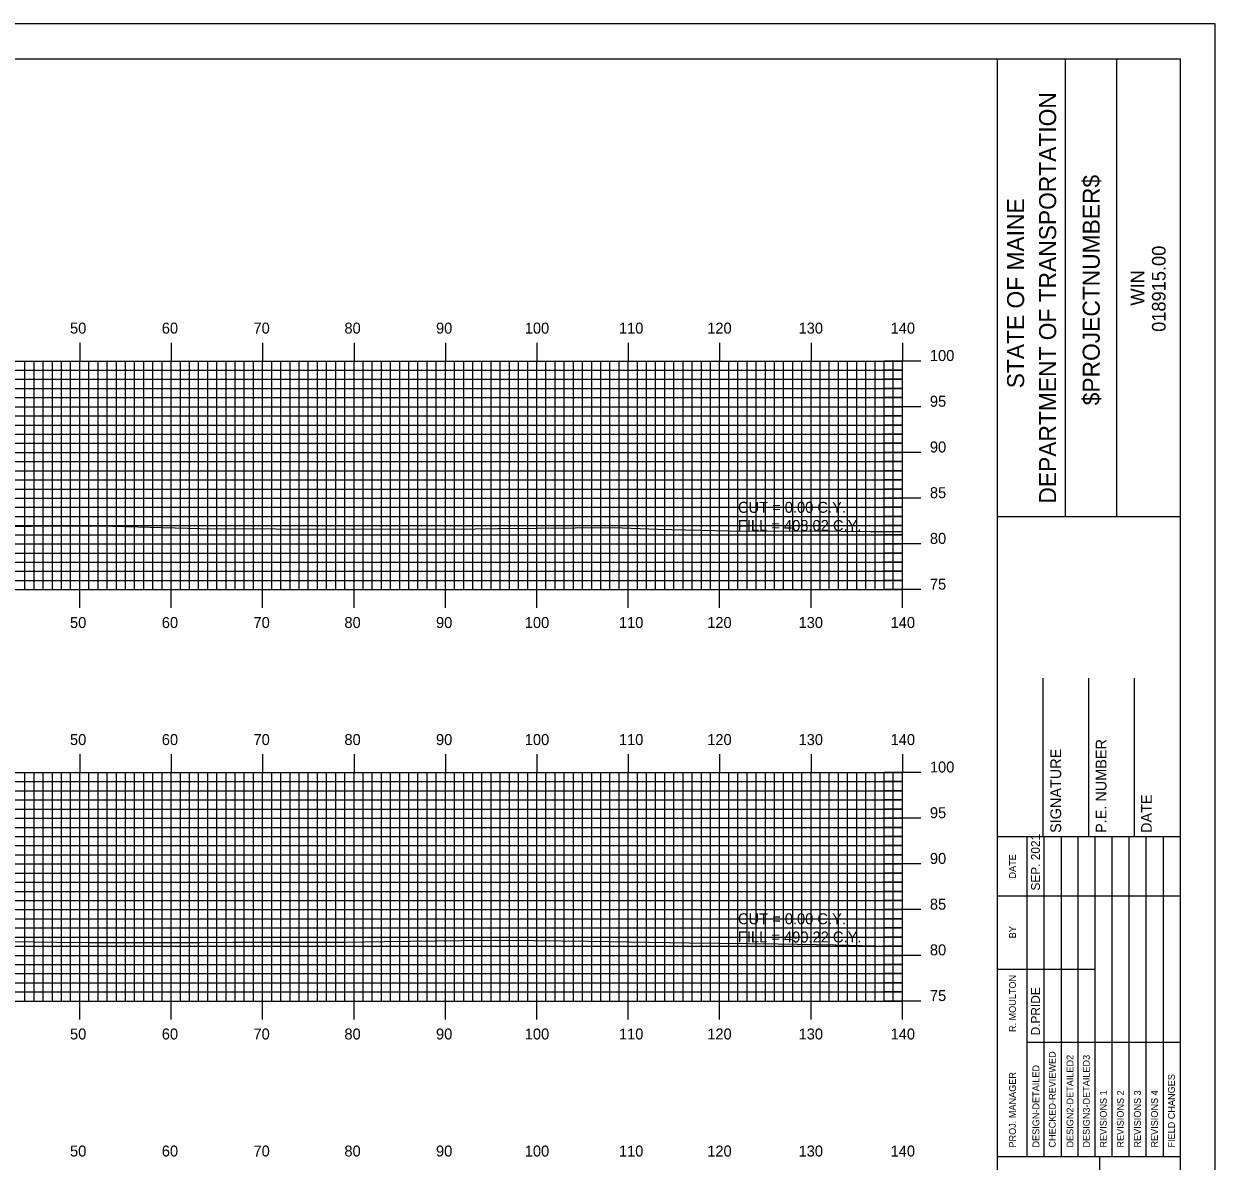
# Model space of a CAD drawing. Extents: x 853723 to 854066, y 364366 to 364586.
# Drawn here: x 853932.6 to 854062.9, y 364461.3 to 364585.7 of the extents above; entities that cross this region are included whole.
import ezdxf

# ---------------------------------------------------------------- set-up
doc = ezdxf.new("R2010")
doc.units = 0
for name, color, linetype in [('BORDER', 7, 'Continuous'), ('D_Text_Standard', 7, 'Continuous'), ('H_V ANNOTATION', 7, 'Continuous'), ('MAJOR', 7, 'Continuous'), ('MINOR', 7, 'Continuous'), ('PLOT BOUNDARY', 7, 'Continuous'), ('S_Roadway_Centerline', 7, 'Continuous')]:
    doc.layers.add(name, color=color, linetype=linetype)

msp = doc.modelspace()

# ---------------------------------------------------------------- linework, layer by layer
at = {"layer": 'BORDER'}
for p, q in [((854039.12, 364371.79), (854039.12, 364581.79)), ((854046.57, 364531.78), (854046.57, 364581.78)), ((854052.16, 364531.78), (854052.16, 364581.78)), ((854039.12, 364531.78), (854059.12, 364531.78)), ((854044.12, 364496.79), (854044.12, 364514.09)), ((854049.12, 364496.79), (854049.12, 364514.09)), ((854054.12, 364496.79), (854054.12, 364514.09)), ((854039.12, 364496.79), (854059.12, 364496.79)), ((854039.12, 364461.79), (854059.12, 364461.79)), ((854050.3, 364391.79), (854050.3, 364461.79))]:
    msp.add_line(p, q, dxfattribs=at)
msp.add_lwpolyline([(853739.12, 364371.79), (854059.12, 364371.79), (854059.12, 364581.79), (853739.12, 364581.79)], close=True, dxfattribs=at)
for points in [[(854042.35, 364490.29), (854042.35, 364496.79)], [(854044.21, 364461.8), (854044.21, 364496.79)], [(854046.08, 364496.79), (854046.08, 364461.8)], [(854047.94, 364461.8), (854047.94, 364496.79)], [(854049.8, 364461.8), (854049.8, 364496.79)], [(854051.67, 364461.8), (854051.67, 364496.79)], [(854053.53, 364461.8), (854053.53, 364496.79)], [(854055.39, 364461.8), (854055.39, 364496.79)], [(854057.26, 364461.8), (854057.26, 364496.79)], [(854042.35, 364461.8), (854042.35, 364495.38)], [(854039.12, 364490.29), (854059.12, 364490.29)], [(854039.12, 364482.29), (854042.35, 364482.29)], [(854042.35, 364482.29), (854049.8, 364482.29)], [(854042.35, 364474.29), (854059.12, 364474.29)]]:
    msp.add_lwpolyline(points, dxfattribs=at)
at = {"layer": 'MAJOR'}
for p, q in [((853938.72, 364550.79), (853938.72, 364548.79)), ((853948.72, 364550.79), (853948.72, 364548.79)), ((853958.72, 364550.79), (853958.72, 364548.79)), ((853968.72, 364550.79), (853968.72, 364548.79)), ((853978.72, 364550.79), (853978.72, 364548.79)), ((853988.72, 364550.79), (853988.72, 364548.79)), ((853998.72, 364550.79), (853998.72, 364548.79)), ((854008.72, 364550.79), (854008.72, 364548.79)), ((854018.72, 364550.79), (854018.72, 364548.79)), ((854028.72, 364550.79), (854028.72, 364548.79)), ((853748.72, 364548.79), (854028.72, 364548.79)), ((853748.72, 364548.79), (854028.72, 364548.79)), ((853938.72, 364523.79), (853938.72, 364548.79)), ((853948.72, 364523.79), (853948.72, 364548.79)), ((853958.72, 364523.79), (853958.72, 364548.79)), ((853968.72, 364523.79), (853968.72, 364548.79)), ((853978.72, 364523.79), (853978.72, 364548.79)), ((853988.72, 364523.79), (853988.72, 364548.79)), ((853998.72, 364523.79), (853998.72, 364548.79)), ((854008.72, 364523.79), (854008.72, 364548.79)), ((854018.72, 364523.79), (854018.72, 364548.79)), ((854030.72, 364548.79), (854026.71, 364548.79)), ((854028.72, 364523.79), (854028.72, 364548.79)), ((854028.72, 364523.79), (854028.72, 364548.79)), ((853748.72, 364543.79), (854028.72, 364543.79)), ((854030.72, 364543.79), (854026.71, 364543.79)), ((853748.72, 364538.79), (854028.72, 364538.79)), ((854030.72, 364538.79), (854026.71, 364538.79)), ((853748.72, 364533.79), (854028.72, 364533.79)), ((854030.72, 364533.79), (854026.71, 364533.79)), ((853748.72, 364528.79), (854028.72, 364528.79)), ((854030.72, 364528.79), (854026.71, 364528.79)), ((853748.72, 364523.79), (854028.72, 364523.79)), ((853748.72, 364523.79), (854028.72, 364523.79)), ((853938.72, 364521.78), (853938.72, 364523.79)), ((853948.72, 364521.78), (853948.72, 364523.79)), ((853958.72, 364521.78), (853958.72, 364523.79)), ((853968.72, 364521.78), (853968.72, 364523.79)), ((853978.72, 364521.78), (853978.72, 364523.79)), ((853988.72, 364521.78), (853988.72, 364523.79)), ((853998.72, 364521.78), (853998.72, 364523.79)), ((854008.72, 364521.78), (854008.72, 364523.79)), ((854018.72, 364521.78), (854018.72, 364523.79)), ((854030.72, 364523.79), (854026.71, 364523.79)), ((854028.72, 364521.78), (854028.72, 364523.79)), ((853938.72, 364505.79), (853938.72, 364503.79)), ((853948.72, 364505.79), (853948.72, 364503.79)), ((853958.72, 364505.79), (853958.72, 364503.79)), ((853968.72, 364505.79), (853968.72, 364503.79)), ((853978.72, 364505.79), (853978.72, 364503.79)), ((853988.72, 364505.79), (853988.72, 364503.79)), ((853998.72, 364505.79), (853998.72, 364503.79)), ((854008.72, 364505.79), (854008.72, 364503.79)), ((854018.72, 364505.79), (854018.72, 364503.79)), ((854028.72, 364505.79), (854028.72, 364503.79)), ((853748.72, 364503.79), (854028.72, 364503.79)), ((853748.72, 364503.79), (854028.72, 364503.79)), ((853938.72, 364478.79), (853938.72, 364503.79)), ((853948.72, 364478.79), (853948.72, 364503.79)), ((853958.72, 364478.79), (853958.72, 364503.79)), ((853968.72, 364478.79), (853968.72, 364503.79)), ((853978.72, 364478.79), (853978.72, 364503.79)), ((853988.72, 364478.79), (853988.72, 364503.79)), ((853998.72, 364478.79), (853998.72, 364503.79)), ((854008.72, 364478.79), (854008.72, 364503.79)), ((854018.72, 364478.79), (854018.72, 364503.79)), ((854030.72, 364503.79), (854026.71, 364503.79)), ((854028.72, 364478.79), (854028.72, 364503.79)), ((854028.72, 364478.79), (854028.72, 364503.79)), ((853748.72, 364498.79), (854028.72, 364498.79)), ((854030.72, 364498.79), (854026.71, 364498.79)), ((853748.72, 364493.79), (854028.72, 364493.79)), ((854030.72, 364493.79), (854026.71, 364493.79)), ((853748.72, 364488.79), (854028.72, 364488.79)), ((854030.72, 364488.79), (854026.71, 364488.79)), ((853748.72, 364483.79), (854028.72, 364483.79)), ((854030.72, 364483.79), (854026.71, 364483.79)), ((853748.72, 364478.79), (854028.72, 364478.79)), ((853748.72, 364478.79), (854028.72, 364478.79)), ((853938.72, 364476.78), (853938.72, 364478.79)), ((853948.72, 364476.78), (853948.72, 364478.79)), ((853958.72, 364476.78), (853958.72, 364478.79)), ((853968.72, 364476.78), (853968.72, 364478.79)), ((853978.72, 364476.78), (853978.72, 364478.79)), ((853988.72, 364476.78), (853988.72, 364478.79)), ((853998.72, 364476.78), (853998.72, 364478.79)), ((854008.72, 364476.78), (854008.72, 364478.79)), ((854018.72, 364476.78), (854018.72, 364478.79)), ((854030.72, 364478.79), (854026.71, 364478.79)), ((854028.72, 364476.78), (854028.72, 364478.79))]:
    msp.add_line(p, q, dxfattribs=at)
at = {"layer": 'MINOR'}
for p, q in [((853748.72, 364547.79), (854028.72, 364547.79)), ((853932.72, 364523.79), (853932.72, 364548.79)), ((853933.72, 364523.79), (853933.72, 364548.79)), ((853934.72, 364523.79), (853934.72, 364548.79)), ((853935.72, 364523.79), (853935.72, 364548.79)), ((853936.72, 364523.79), (853936.72, 364548.79)), ((853937.72, 364523.79), (853937.72, 364548.79)), ((853939.72, 364523.79), (853939.72, 364548.79)), ((853940.72, 364523.79), (853940.72, 364548.79)), ((853941.72, 364523.79), (853941.72, 364548.79)), ((853942.72, 364523.79), (853942.72, 364548.79)), ((853943.72, 364523.79), (853943.72, 364548.79)), ((853944.72, 364523.79), (853944.72, 364548.79)), ((853945.72, 364523.79), (853945.72, 364548.79)), ((853946.72, 364523.79), (853946.72, 364548.79)), ((853947.72, 364523.79), (853947.72, 364548.79)), ((853949.72, 364523.79), (853949.72, 364548.79)), ((853950.72, 364523.79), (853950.72, 364548.79)), ((853951.72, 364523.79), (853951.72, 364548.79)), ((853952.72, 364523.79), (853952.72, 364548.79)), ((853953.72, 364523.79), (853953.72, 364548.79)), ((853954.72, 364523.79), (853954.72, 364548.79)), ((853955.72, 364523.79), (853955.72, 364548.79)), ((853956.72, 364523.79), (853956.72, 364548.79)), ((853957.72, 364523.79), (853957.72, 364548.79)), ((853959.72, 364523.79), (853959.72, 364548.79)), ((853960.72, 364523.79), (853960.72, 364548.79)), ((853961.72, 364523.79), (853961.72, 364548.79)), ((853962.72, 364523.79), (853962.72, 364548.79)), ((853963.72, 364523.79), (853963.72, 364548.79)), ((853964.72, 364523.79), (853964.72, 364548.79)), ((853965.72, 364523.79), (853965.72, 364548.79)), ((853966.72, 364523.79), (853966.72, 364548.79)), ((853967.72, 364523.79), (853967.72, 364548.79)), ((853969.72, 364523.79), (853969.72, 364548.79)), ((853970.72, 364523.79), (853970.72, 364548.79)), ((853971.72, 364523.79), (853971.72, 364548.79)), ((853972.72, 364523.79), (853972.72, 364548.79)), ((853973.72, 364523.79), (853973.72, 364548.79)), ((853974.72, 364523.79), (853974.72, 364548.79)), ((853975.72, 364523.79), (853975.72, 364548.79)), ((853976.72, 364523.79), (853976.72, 364548.79)), ((853977.72, 364523.79), (853977.72, 364548.79)), ((853979.72, 364523.79), (853979.72, 364548.79)), ((853980.72, 364523.79), (853980.72, 364548.79)), ((853981.72, 364523.79), (853981.72, 364548.79)), ((853982.72, 364523.79), (853982.72, 364548.79)), ((853983.72, 364523.79), (853983.72, 364548.79)), ((853984.72, 364523.79), (853984.72, 364548.79)), ((853985.72, 364523.79), (853985.72, 364548.79)), ((853986.72, 364523.79), (853986.72, 364548.79)), ((853987.72, 364523.79), (853987.72, 364548.79)), ((853989.72, 364523.79), (853989.72, 364548.79)), ((853990.72, 364523.79), (853990.72, 364548.79)), ((853991.72, 364523.79), (853991.72, 364548.79)), ((853992.72, 364523.79), (853992.72, 364548.79)), ((853993.72, 364523.79), (853993.72, 364548.79)), ((853994.72, 364523.79), (853994.72, 364548.79)), ((853995.72, 364523.79), (853995.72, 364548.79)), ((853996.72, 364523.79), (853996.72, 364548.79)), ((853997.72, 364523.79), (853997.72, 364548.79)), ((853999.72, 364523.79), (853999.72, 364548.79)), ((854000.72, 364523.79), (854000.72, 364548.79)), ((854001.72, 364523.79), (854001.72, 364548.79)), ((854002.72, 364523.79), (854002.72, 364548.79)), ((854003.72, 364523.79), (854003.72, 364548.79)), ((854004.72, 364523.79), (854004.72, 364548.79)), ((854005.72, 364523.79), (854005.72, 364548.79)), ((854006.72, 364523.79), (854006.72, 364548.79)), ((854007.72, 364523.79), (854007.72, 364548.79)), ((854009.72, 364523.79), (854009.72, 364548.79)), ((854010.72, 364523.79), (854010.72, 364548.79)), ((854011.72, 364523.79), (854011.72, 364548.79)), ((854012.72, 364523.79), (854012.72, 364548.79)), ((854013.72, 364523.79), (854013.72, 364548.79)), ((854014.72, 364523.79), (854014.72, 364548.79)), ((854015.72, 364523.79), (854015.72, 364548.79)), ((854016.72, 364523.79), (854016.72, 364548.79)), ((854017.72, 364523.79), (854017.72, 364548.79)), ((854019.72, 364523.79), (854019.72, 364548.79)), ((854020.72, 364523.79), (854020.72, 364548.79)), ((854021.72, 364523.79), (854021.72, 364548.79)), ((854022.72, 364523.79), (854022.72, 364548.79)), ((854023.72, 364523.79), (854023.72, 364548.79)), ((854024.72, 364523.79), (854024.72, 364548.79)), ((854025.72, 364523.79), (854025.72, 364548.79)), ((854028.72, 364547.79), (854026.71, 364547.79)), ((854026.72, 364523.79), (854026.72, 364548.79)), ((854027.72, 364523.79), (854027.72, 364548.79)), ((853748.72, 364546.79), (854028.72, 364546.79)), ((854028.72, 364546.79), (854026.71, 364546.79)), ((853748.72, 364545.79), (854028.72, 364545.79)), ((854028.72, 364545.79), (854026.71, 364545.79)), ((853748.72, 364544.79), (854028.72, 364544.79)), ((854028.72, 364544.79), (854026.71, 364544.79)), ((853748.72, 364542.79), (854028.72, 364542.79)), ((854028.72, 364542.79), (854026.71, 364542.79)), ((853748.72, 364541.79), (854028.72, 364541.79)), ((854028.72, 364541.79), (854026.71, 364541.79)), ((853748.72, 364540.79), (854028.72, 364540.79)), ((854028.72, 364540.79), (854026.71, 364540.79)), ((853748.72, 364539.79), (854028.72, 364539.79)), ((854028.72, 364539.79), (854026.71, 364539.79)), ((853748.72, 364537.79), (854028.72, 364537.79)), ((854028.72, 364537.79), (854026.71, 364537.79)), ((853748.72, 364536.79), (854028.72, 364536.79)), ((854028.72, 364536.79), (854026.71, 364536.79)), ((853748.72, 364535.79), (854028.72, 364535.79)), ((853748.72, 364534.79), (854028.72, 364534.79)), ((854028.72, 364535.79), (854026.71, 364535.79)), ((854028.72, 364534.79), (854026.71, 364534.79)), ((853748.72, 364532.79), (854028.72, 364532.79)), ((854028.72, 364532.79), (854026.71, 364532.79)), ((853748.72, 364531.79), (854028.72, 364531.79)), ((853748.72, 364530.79), (854028.72, 364530.79)), ((854028.72, 364531.79), (854026.71, 364531.79)), ((854028.72, 364530.79), (854026.71, 364530.79)), ((853748.72, 364529.79), (854028.72, 364529.79)), ((854028.72, 364529.79), (854026.71, 364529.79)), ((853748.72, 364527.79), (854028.72, 364527.79)), ((853748.72, 364526.79), (854028.72, 364526.79)), ((854028.72, 364527.79), (854026.71, 364527.79)), ((854028.72, 364526.79), (854026.71, 364526.79)), ((853748.72, 364525.79), (854028.72, 364525.79)), ((854028.72, 364525.79), (854026.71, 364525.79)), ((853748.72, 364524.79), (854028.72, 364524.79)), ((854028.72, 364524.79), (854026.71, 364524.79)), ((853932.72, 364478.79), (853932.72, 364503.79)), ((853933.72, 364478.79), (853933.72, 364503.79)), ((853934.72, 364478.79), (853934.72, 364503.79)), ((853935.72, 364478.79), (853935.72, 364503.79)), ((853936.72, 364478.79), (853936.72, 364503.79)), ((853937.72, 364478.79), (853937.72, 364503.79)), ((853939.72, 364478.79), (853939.72, 364503.79)), ((853940.72, 364478.79), (853940.72, 364503.79)), ((853941.72, 364478.79), (853941.72, 364503.79)), ((853942.72, 364478.79), (853942.72, 364503.79)), ((853943.72, 364478.79), (853943.72, 364503.79)), ((853944.72, 364478.79), (853944.72, 364503.79)), ((853945.72, 364478.79), (853945.72, 364503.79)), ((853946.72, 364478.79), (853946.72, 364503.79)), ((853947.72, 364478.79), (853947.72, 364503.79)), ((853949.72, 364478.79), (853949.72, 364503.79)), ((853950.72, 364478.79), (853950.72, 364503.79)), ((853951.72, 364478.79), (853951.72, 364503.79)), ((853952.72, 364478.79), (853952.72, 364503.79)), ((853953.72, 364478.79), (853953.72, 364503.79)), ((853954.72, 364478.79), (853954.72, 364503.79)), ((853955.72, 364478.79), (853955.72, 364503.79)), ((853956.72, 364478.79), (853956.72, 364503.79)), ((853957.72, 364478.79), (853957.72, 364503.79)), ((853959.72, 364478.79), (853959.72, 364503.79)), ((853960.72, 364478.79), (853960.72, 364503.79)), ((853961.72, 364478.79), (853961.72, 364503.79)), ((853962.72, 364478.79), (853962.72, 364503.79)), ((853963.72, 364478.79), (853963.72, 364503.79)), ((853964.72, 364478.79), (853964.72, 364503.79)), ((853965.72, 364478.79), (853965.72, 364503.79)), ((853966.72, 364478.79), (853966.72, 364503.79)), ((853967.72, 364478.79), (853967.72, 364503.79)), ((853969.72, 364478.79), (853969.72, 364503.79)), ((853970.72, 364478.79), (853970.72, 364503.79)), ((853971.72, 364478.79), (853971.72, 364503.79)), ((853972.72, 364478.79), (853972.72, 364503.79)), ((853973.72, 364478.79), (853973.72, 364503.79)), ((853974.72, 364478.79), (853974.72, 364503.79)), ((853975.72, 364478.79), (853975.72, 364503.79)), ((853976.72, 364478.79), (853976.72, 364503.79)), ((853977.72, 364478.79), (853977.72, 364503.79)), ((853979.72, 364478.79), (853979.72, 364503.79)), ((853980.72, 364478.79), (853980.72, 364503.79)), ((853981.72, 364478.79), (853981.72, 364503.79)), ((853982.72, 364478.79), (853982.72, 364503.79)), ((853983.72, 364478.79), (853983.72, 364503.79)), ((853984.72, 364478.79), (853984.72, 364503.79)), ((853985.72, 364478.79), (853985.72, 364503.79)), ((853986.72, 364478.79), (853986.72, 364503.79)), ((853987.72, 364478.79), (853987.72, 364503.79)), ((853989.72, 364478.79), (853989.72, 364503.79)), ((853990.72, 364478.79), (853990.72, 364503.79)), ((853991.72, 364478.79), (853991.72, 364503.79)), ((853992.72, 364478.79), (853992.72, 364503.79)), ((853993.72, 364478.79), (853993.72, 364503.79)), ((853994.72, 364478.79), (853994.72, 364503.79)), ((853995.72, 364478.79), (853995.72, 364503.79)), ((853996.72, 364478.79), (853996.72, 364503.79)), ((853997.72, 364478.79), (853997.72, 364503.79)), ((853999.72, 364478.79), (853999.72, 364503.79)), ((854000.72, 364478.79), (854000.72, 364503.79)), ((854001.72, 364478.79), (854001.72, 364503.79)), ((854002.72, 364478.79), (854002.72, 364503.79)), ((854003.72, 364478.79), (854003.72, 364503.79)), ((854004.72, 364478.79), (854004.72, 364503.79)), ((854005.72, 364478.79), (854005.72, 364503.79)), ((854006.72, 364478.79), (854006.72, 364503.79)), ((854007.72, 364478.79), (854007.72, 364503.79)), ((854009.72, 364478.79), (854009.72, 364503.79)), ((854010.72, 364478.79), (854010.72, 364503.79)), ((854011.72, 364478.79), (854011.72, 364503.79)), ((854012.72, 364478.79), (854012.72, 364503.79)), ((854013.72, 364478.79), (854013.72, 364503.79)), ((854014.72, 364478.79), (854014.72, 364503.79)), ((854015.72, 364478.79), (854015.72, 364503.79)), ((854016.72, 364478.79), (854016.72, 364503.79)), ((854017.72, 364478.79), (854017.72, 364503.79)), ((854019.72, 364478.79), (854019.72, 364503.79)), ((854020.72, 364478.79), (854020.72, 364503.79)), ((854021.72, 364478.79), (854021.72, 364503.79)), ((854022.72, 364478.79), (854022.72, 364503.79)), ((854023.72, 364478.79), (854023.72, 364503.79)), ((854024.72, 364478.79), (854024.72, 364503.79)), ((854025.72, 364478.79), (854025.72, 364503.79)), ((854026.72, 364478.79), (854026.72, 364503.79)), ((854027.72, 364478.79), (854027.72, 364503.79)), ((853748.72, 364502.79), (854028.72, 364502.79)), ((854028.72, 364502.79), (854026.71, 364502.79)), ((853748.72, 364501.79), (854028.72, 364501.79)), ((853748.72, 364500.79), (854028.72, 364500.79)), ((854028.72, 364501.79), (854026.71, 364501.79)), ((854028.72, 364500.79), (854026.71, 364500.79)), ((853748.72, 364499.79), (854028.72, 364499.79)), ((854028.72, 364499.79), (854026.71, 364499.79)), ((853748.72, 364497.79), (854028.72, 364497.79)), ((854028.72, 364497.79), (854026.71, 364497.79)), ((853748.72, 364496.79), (854028.72, 364496.79)), ((853748.72, 364495.79), (854028.72, 364495.79)), ((854028.72, 364496.79), (854026.71, 364496.79)), ((854028.72, 364495.79), (854026.71, 364495.79)), ((853748.72, 364494.79), (854028.72, 364494.79)), ((854028.72, 364494.79), (854026.71, 364494.79)), ((853748.72, 364492.79), (854028.72, 364492.79)), ((853748.72, 364491.79), (854028.72, 364491.79)), ((854028.72, 364492.79), (854026.71, 364492.79)), ((854028.72, 364491.79), (854026.71, 364491.79)), ((853748.72, 364490.79), (854028.72, 364490.79)), ((854028.72, 364490.79), (854026.71, 364490.79)), ((853748.72, 364489.79), (854028.72, 364489.79)), ((854028.72, 364489.79), (854026.71, 364489.79)), ((853748.72, 364487.79), (854028.72, 364487.79)), ((854028.72, 364487.79), (854026.71, 364487.79)), ((853748.72, 364486.79), (854028.72, 364486.79)), ((854028.72, 364486.79), (854026.71, 364486.79)), ((853748.72, 364485.79), (854028.72, 364485.79)), ((854028.72, 364485.79), (854026.71, 364485.79)), ((853748.72, 364484.79), (854028.72, 364484.79)), ((854028.72, 364484.79), (854026.71, 364484.79)), ((853748.72, 364482.79), (854028.72, 364482.79)), ((854028.72, 364482.79), (854026.71, 364482.79)), ((853748.72, 364481.79), (854028.72, 364481.79)), ((854028.72, 364481.79), (854026.71, 364481.79)), ((853748.72, 364480.79), (854028.72, 364480.79)), ((854028.72, 364480.79), (854026.71, 364480.79)), ((853748.72, 364479.79), (854028.72, 364479.79)), ((854028.72, 364479.79), (854026.71, 364479.79))]:
    msp.add_line(p, q, dxfattribs=at)
at = {"layer": 'PLOT BOUNDARY'}
msp.add_lwpolyline([(853722.93, 364365.67), (854062.93, 364365.67), (854062.93, 364585.67), (853722.93, 364585.67)], close=True, dxfattribs=at)
at = {"layer": 'S_Roadway_Centerline'}
for points in [[(853926.17, 364530.58), (853935.19, 364530.75), (853940.94, 364530.77), (853951.88, 364530.49), (853968.52, 364530.4), (853968.62, 364530.4), (853981.97, 364530.42), (853984.48, 364530.48), (853997.15, 364530.59), (854001.92, 364530.4), (854011.24, 364530.2), (854018.74, 364530.23), (854025.25, 364530.15), (854028.72, 364530.15)], [(853923.41, 364485.4), (853936.21, 364485.25), (853939.67, 364485.2), (853951.89, 364485.18), (853955.49, 364485.24), (853967.72, 364485.25), (853972.07, 364485.3), (853983.27, 364485.44), (853988.43, 364485.42), (853994.38, 364485.35), (854005.38, 364485.17), (854015.13, 364485.04), (854021.41, 364484.95), (854027.34, 364484.81), (854028.72, 364484.79)]]:
    msp.add_lwpolyline(points, dxfattribs=at)

# ---------------------------------------------------------------- texts
at = {"layer": 'BORDER'}
for s, height, p in [('DEPARTMENT OF TRANSPORTATION', 1.8635, (854045.53, 364533.2)), ('$PROJECTNUMBER$', 1.8635, (854050.3, 364543.95)), ('STATE OF MAINE', 1.8635, (854042.03, 364545.81)), ('018915.00', 1.491, (854057.51, 364551.98)), ('WIN', 1.491, (854055.19, 364554.85)), ('P.E. NUMBER', 1.1811, (854051.04, 364497.18)), ('SIGNATURE', 1.181, (854046.08, 364497.18)), ('DATE', 1.181, (854056, 364497.18)), ('SEP. 2021', 0.969, (854043.76, 364490.88)), ('DATE', 0.743, (854041.13, 364492.2)), ('BY', 0.743, (854041.13, 364485.66)), ('R. MOULTON', 0.745, (854041.13, 364475.4)), ('D.PRIDE', 0.969, (854043.76, 364475.04)), ('CHECKED-REVIEWED', 0.7455, (854045.48, 364462.77)), ('DESIGN2-DETAILED2', 0.7455, (854047.42, 364462.77)), ('DESIGN3-DETAILED3', 0.7455, (854049.21, 364462.77)), ('PROJ. MANAGER', 0.7455, (854041.13, 364462.77)), ('DESIGN-DETAILED', 0.7455, (854043.69, 364462.77)), ('FIELD CHANGES', 0.7455, (854058.52, 364462.77)), ('REVISIONS 1', 0.7455, (854051.07, 364462.77)), ('REVISIONS 2', 0.7455, (854052.93, 364462.77)), ('REVISIONS 3', 0.7455, (854054.8, 364462.77)), ('REVISIONS 4', 0.7455, (854056.66, 364462.77))]:
    msp.add_text(s, height=height, rotation=90, dxfattribs=at).set_placement(p)
at = {"layer": 'D_Text_Standard'}
for s, p in [('CUT = 0.00 C.Y.', (854010.72, 364532.19)), ('FILL = 408.02 C.Y.', (854010.72, 364530.2)), ('CUT = 0.00 C.Y.', (854010.72, 364487.19)), ('FILL = 490.22 C.Y.', (854010.72, 364485.2))]:
    msp.add_text(s, height=1.2, dxfattribs=at).set_placement(p)
at = {"layer": 'H_V ANNOTATION'}
for s, p in [('50', (853937.65, 364551.79)), ('60', (853947.69, 364551.79)), ('70', (853957.72, 364551.79)), ('80', (853967.67, 364551.79)), ('90', (853977.69, 364551.79)), ('100', (853987.4, 364551.79)), ('110', (853997.7, 364551.79)), ('120', (854007.36, 364551.79)), ('130', (854017.35, 364551.79)), ('140', (854027.42, 364551.79)), ('100', (854031.72, 364548.79)), ('95', (854031.72, 364543.79)), ('90', (854031.72, 364538.79)), ('85', (854031.72, 364533.79)), ('80', (854031.72, 364528.79)), ('75', (854031.72, 364523.79)), ('50', (853937.65, 364519.59)), ('60', (853947.69, 364519.59)), ('70', (853957.72, 364519.59)), ('80', (853967.67, 364519.59)), ('90', (853977.69, 364519.59)), ('100', (853987.4, 364519.59)), ('110', (853997.7, 364519.59)), ('120', (854007.36, 364519.59)), ('130', (854017.35, 364519.59)), ('140', (854027.42, 364519.59)), ('50', (853937.65, 364506.79)), ('60', (853947.69, 364506.79)), ('70', (853957.72, 364506.79)), ('80', (853967.67, 364506.79)), ('90', (853977.69, 364506.79)), ('100', (853987.4, 364506.79)), ('110', (853997.7, 364506.79)), ('120', (854007.36, 364506.79)), ('130', (854017.35, 364506.79)), ('140', (854027.42, 364506.79)), ('100', (854031.72, 364503.79)), ('95', (854031.72, 364498.79)), ('90', (854031.72, 364493.79)), ('85', (854031.72, 364488.79)), ('80', (854031.72, 364483.79)), ('75', (854031.72, 364478.79)), ('50', (853937.65, 364474.59)), ('60', (853947.69, 364474.59)), ('70', (853957.72, 364474.59)), ('80', (853967.67, 364474.59)), ('90', (853977.69, 364474.59)), ('100', (853987.4, 364474.59)), ('110', (853997.7, 364474.59)), ('120', (854007.36, 364474.59)), ('130', (854017.35, 364474.59)), ('140', (854027.42, 364474.59)), ('50', (853937.65, 364461.79)), ('60', (853947.69, 364461.79)), ('70', (853957.72, 364461.79)), ('80', (853967.67, 364461.79)), ('90', (853977.69, 364461.79)), ('100', (853987.4, 364461.79)), ('110', (853997.7, 364461.79)), ('120', (854007.36, 364461.79)), ('130', (854017.35, 364461.79)), ('140', (854027.42, 364461.79))]:
    msp.add_text(s, height=1.2, dxfattribs=at).set_placement(p)

doc.saveas('drawing.dxf')
